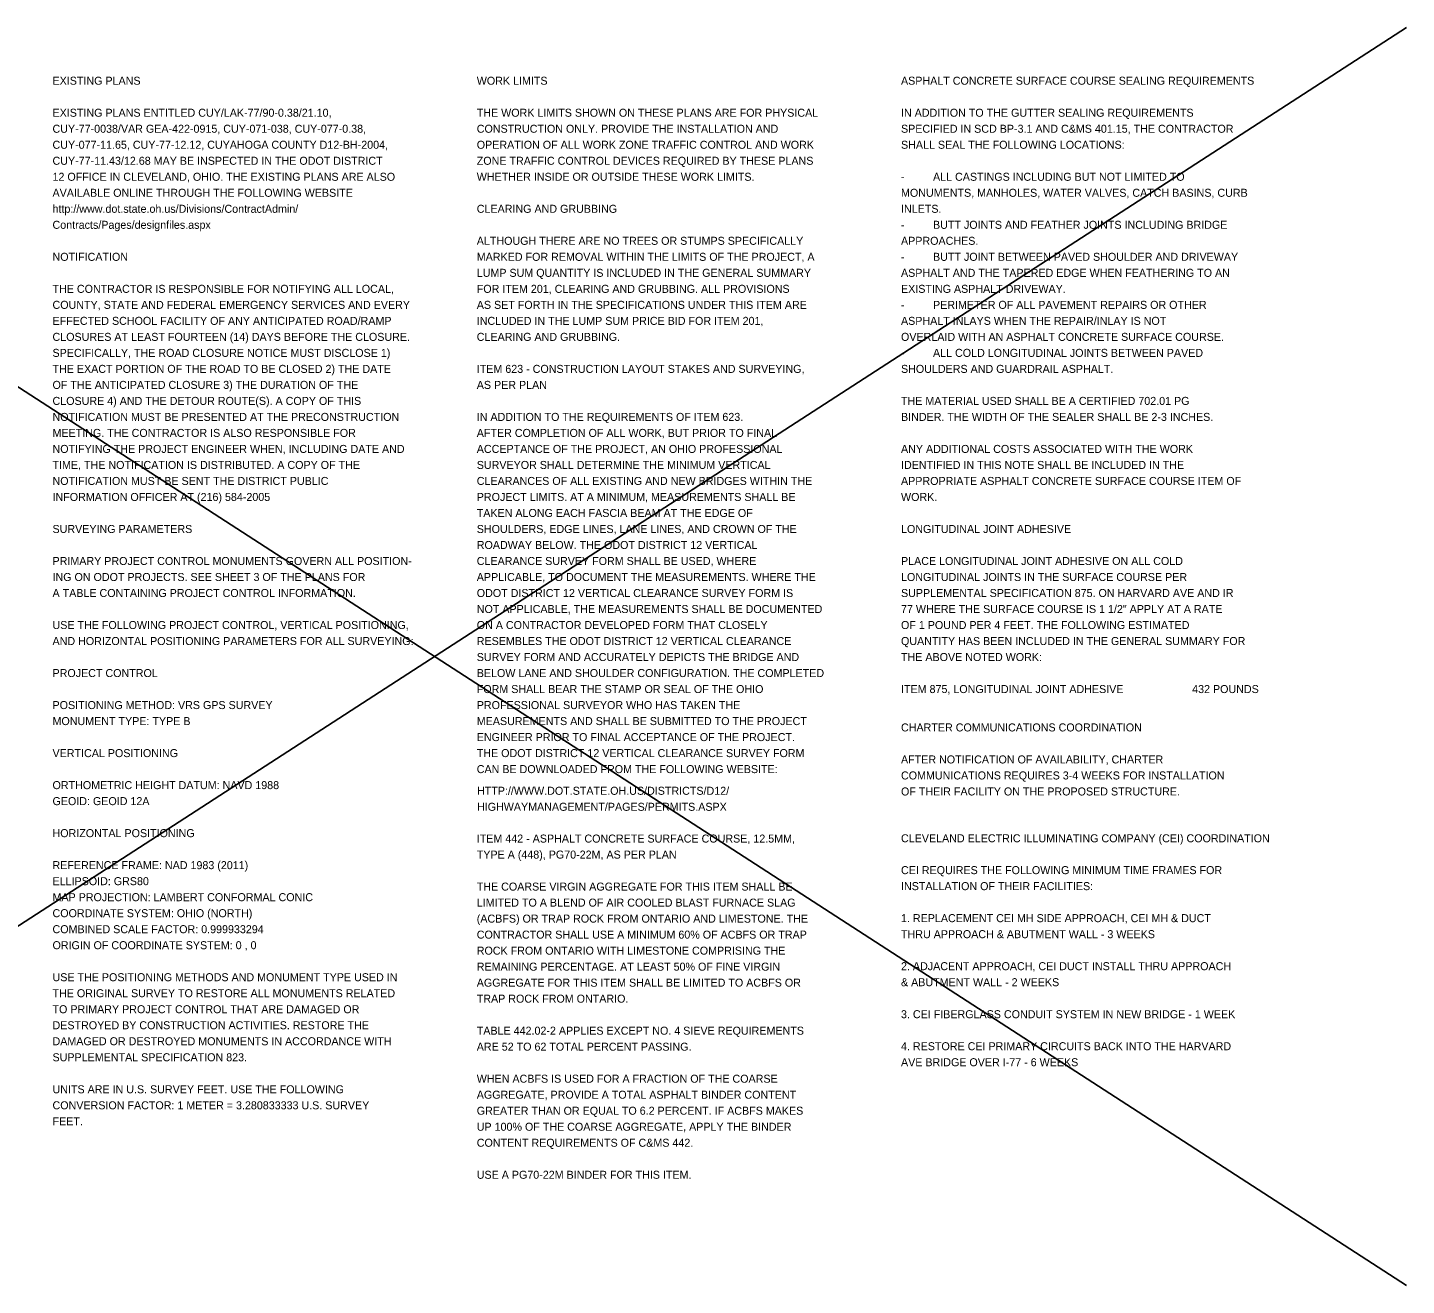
# Model space of a CAD drawing. Extents: x -9 to 100, y -25 to 48.
# Drawn here: x 10.02 to 34.14, y 25.8 to 47.8 of the extents above; entities that cross this region are included whole.
import ezdxf

# ---------------------------------------------------------------- set-up
doc = ezdxf.new("R2010")
doc.units = 0
doc.layers.add('Default', color=7, linetype='Continuous')
doc.layers.add('SH_Text', color=7, linetype='Continuous')

msp = doc.modelspace()

# ---------------------------------------------------------------- linework, layer by layer
at = {"layer": 'Default'}
for p, q in [((0.139, 47.801), (34.139, 25.801)), ((0.139, 25.801), (34.139, 47.801))]:
    msp.add_line(p, q, dxfattribs=at)

# ---------------------------------------------------------------- texts
at = {"layer": 'SH_Text'}
for s, p in [('EXISTING PLANS', (10.459, 46.801)), ('WORK LIMITS', (17.879, 46.801)), ('ASPHALT CONCRETE SURFACE COURSE SEALING REQUIREMENTS', (25.299, 46.801)), ('EXISTING PLANS ENTITLED CUY/LAK-77/90-0.38/21.10, ', (10.459, 46.241)), ('THE WORK LIMITS SHOWN ON THESE PLANS ARE FOR PHYSICAL', (17.879, 46.241)), ('IN ADDITION TO THE GUTTER SEALING REQUIREMENTS ', (25.299, 46.241)), ('CUY-77-0038/VAR GEA-422-0915, CUY-071-038, CUY-077-0.38, ', (10.459, 45.961)), ('CONSTRUCTION ONLY. PROVIDE THE INSTALLATION AND', (17.879, 45.961)), ('SPECIFIED IN SCD BP-3.1 AND C&MS 401.15, THE CONTRACTOR ', (25.299, 45.961)), ('CUY-077-11.65, CUY-77-12.12, CUYAHOGA COUNTY D12-BH-2004, ', (10.459, 45.681)), ('OPERATION OF ALL WORK ZONE TRAFFIC CONTROL AND WORK', (17.879, 45.681)), ('SHALL SEAL THE FOLLOWING LOCATIONS:', (25.299, 45.681)), ('CUY-77-11.43/12.68 MAY BE INSPECTED IN THE ODOT DISTRICT ', (10.459, 45.401)), ('ZONE TRAFFIC CONTROL DEVICES REQUIRED BY THESE PLANS', (17.879, 45.401)), ('12 OFFICE IN CLEVELAND, OHIO. THE EXISTING PLANS ARE ALSO ', (10.459, 45.121)), ('WHETHER INSIDE OR OUTSIDE THESE WORK LIMITS.', (17.879, 45.121)), ('-', (25.299, 45.121)), ('ALL CASTINGS INCLUDING BUT NOT LIMITED TO  ', (25.859, 45.121)), ('AVAILABLE ONLINE THROUGH THE FOLLOWING WEBSITE', (10.459, 44.841)), ('MONUMENTS, MANHOLES, WATER VALVES, CATCH BASINS, CURB ', (25.299, 44.841)), ('http://www.dot.state.oh.us/Divisions/ContractAdmin/', (10.459, 44.561)), ('CLEARING AND GRUBBING', (17.879, 44.561)), ('INLETS. ', (25.299, 44.561)), ('Contracts/Pages/designfiles.aspx', (10.459, 44.281)), ('BUTT JOINTS AND FEATHER JOINTS INCLUDING BRIDGE ', (25.859, 44.281)), ('ALTHOUGH THERE ARE NO TREES OR STUMPS SPECIFICALLY', (17.879, 44.001)), ('APPROACHES. ', (25.299, 44.001)), ('-', (25.299, 44.281)), ('NOTIFICATION', (10.459, 43.721)), ('MARKED FOR REMOVAL WITHIN THE LIMITS OF THE PROJECT, A', (17.879, 43.721)), ('-', (25.299, 43.721)), ('BUTT JOINT BETWEEN PAVED SHOULDER AND DRIVEWAY ', (25.859, 43.721)), ('LUMP SUM QUANTITY IS INCLUDED IN THE GENERAL SUMMARY', (17.879, 43.441)), ('ASPHALT AND THE TAPERED EDGE WHEN FEATHERING TO AN ', (25.299, 43.441)), ('THE CONTRACTOR IS RESPONSIBLE FOR NOTIFYING ALL LOCAL, ', (10.459, 43.161)), ('FOR ITEM 201, CLEARING AND GRUBBING. ALL PROVISIONS', (17.879, 43.161)), ('EXISTING ASPHALT DRIVEWAY. ', (25.299, 43.161)), ('COUNTY, STATE AND FEDERAL EMERGENCY SERVICES AND EVERY ', (10.459, 42.881)), ('AS SET FORTH IN THE SPECIFICATIONS UNDER THIS ITEM ARE', (17.879, 42.881)), ('-', (25.299, 42.881)), ('PERIMETER OF ALL PAVEMENT REPAIRS OR OTHER ', (25.859, 42.881)), ('EFFECTED SCHOOL FACILITY OF ANY ANTICIPATED ROAD/RAMP ', (10.459, 42.601)), ('INCLUDED IN THE LUMP SUM PRICE BID FOR ITEM 201,', (17.879, 42.601)), ('ASPHALT INLAYS WHEN THE REPAIR/INLAY IS NOT ', (25.299, 42.601)), ('CLOSURES AT LEAST FOURTEEN (14) DAYS BEFORE THE CLOSURE. ', (10.459, 42.321)), ('CLEARING AND GRUBBING.', (17.879, 42.321)), ('OVERLAID WITH AN ASPHALT CONCRETE SURFACE COURSE. ', (25.299, 42.321)), ('SPECIFICALLY, THE ROAD CLOSURE NOTICE MUST DISCLOSE 1) ', (10.459, 42.041)), ('-', (25.299, 42.041)), ('ALL COLD LONGITUDINAL JOINTS BETWEEN PAVED ', (25.859, 42.041)), ('THE EXACT PORTION OF THE ROAD TO BE CLOSED 2) THE DATE ', (10.459, 41.761)), ('ITEM 623 - CONSTRUCTION LAYOUT STAKES AND SURVEYING, ', (17.879, 41.761)), ('SHOULDERS AND GUARDRAIL ASPHALT. ', (25.299, 41.761)), ('OF THE ANTICIPATED CLOSURE 3) THE DURATION OF THE ', (10.459, 41.481)), ('AS PER PLAN', (17.879, 41.481)), ('CLOSURE 4) AND THE DETOUR ROUTE(S). A COPY OF THIS ', (10.459, 41.201)), ('THE MATERIAL USED SHALL BE A CERTIFIED 702.01 PG ', (25.299, 41.201)), ('NOTIFICATION MUST BE PRESENTED AT THE PRECONSTRUCTION ', (10.459, 40.921)), ('IN ADDITION TO THE REQUIREMENTS OF ITEM 623.', (17.879, 40.921)), ('BINDER. THE WIDTH OF THE SEALER SHALL BE 2-3 INCHES. ', (25.299, 40.921)), ('MEETING. THE CONTRACTOR IS ALSO RESPONSIBLE FOR ', (10.459, 40.641)), ('AFTER COMPLETION OF ALL WORK, BUT PRIOR TO FINAL ', (17.879, 40.641)), ('NOTIFYING THE PROJECT ENGINEER WHEN, INCLUDING DATE AND ', (10.459, 40.361)), ('ACCEPTANCE OF THE PROJECT, AN OHIO PROFESSIONAL ', (17.879, 40.361)), ('ANY ADDITIONAL COSTS ASSOCIATED WITH THE WORK ', (25.299, 40.361)), ('TIME, THE NOTIFICATION IS DISTRIBUTED. A COPY OF THE ', (10.459, 40.081)), ('SURVEYOR SHALL DETERMINE THE MINIMUM VERTICAL ', (17.879, 40.081)), ('IDENTIFIED IN THIS NOTE SHALL BE INCLUDED IN THE ', (25.299, 40.081)), ('NOTIFICATION MUST BE SENT THE DISTRICT PUBLIC ', (10.459, 39.801)), ('CLEARANCES OF ALL EXISTING AND NEW BRIDGES WITHIN THE ', (17.879, 39.801)), ('APPROPRIATE ASPHALT CONCRETE SURFACE COURSE ITEM OF ', (25.299, 39.801)), ('INFORMATION OFFICER AT (216) 584-2005', (10.459, 39.521)), ('PROJECT LIMITS. AT A MINIMUM, MEASUREMENTS SHALL BE ', (17.879, 39.521)), ('WORK. ', (25.299, 39.521)), ('TAKEN ALONG EACH FASCIA BEAM AT THE EDGE OF ', (17.879, 39.241)), ('SURVEYING PARAMETERS', (10.459, 38.961)), ('SHOULDERS, EDGE LINES, LANE LINES, AND CROWN OF THE ', (17.879, 38.961)), ('LONGITUDINAL JOINT ADHESIVE', (25.299, 38.961)), ('ROADWAY BELOW. THE ODOT DISTRICT 12 VERTICAL ', (17.879, 38.681)), ('PRIMARY PROJECT CONTROL MONUMENTS GOVERN ALL POSITION-', (10.459, 38.401)), ('CLEARANCE SURVEY FORM SHALL BE USED, WHERE ', (17.879, 38.401)), ('PLACE LONGITUDINAL JOINT ADHESIVE ON ALL COLD ', (25.299, 38.401)), ('ING ON ODOT PROJECTS. SEE SHEET 3 OF THE PLANS FOR', (10.459, 38.121)), ('APPLICABLE, TO DOCUMENT THE MEASUREMENTS. WHERE THE ', (17.879, 38.121)), ('LONGITUDINAL JOINTS IN THE SURFACE COURSE PER ', (25.299, 38.121)), ('A TABLE CONTAINING PROJECT CONTROL INFORMATION.', (10.459, 37.841)), ('ODOT DISTRICT 12 VERTICAL CLEARANCE SURVEY FORM IS ', (17.879, 37.841)), ('SUPPLEMENTAL SPECIFICATION 875. ON HARVARD AVE AND IR ', (25.299, 37.841)), ('NOT APPLICABLE, THE MEASUREMENTS SHALL BE DOCUMENTED ', (17.879, 37.561)), ('77 WHERE THE SURFACE COURSE IS 1 1/2" APPLY AT A RATE ', (25.299, 37.561)), ('USE THE FOLLOWING PROJECT CONTROL, VERTICAL POSITIONING,', (10.459, 37.281)), ('ON A CONTRACTOR DEVELOPED FORM THAT CLOSELY ', (17.879, 37.281)), ('OF 1 POUND PER 4 FEET. THE FOLLOWING ESTIMATED ', (25.299, 37.281)), ('AND HORIZONTAL POSITIONING PARAMETERS FOR ALL SURVEYING:', (10.459, 37.001)), ('RESEMBLES THE ODOT DISTRICT 12 VERTICAL CLEARANCE ', (17.879, 37.001)), ('QUANTITY HAS BEEN INCLUDED IN THE GENERAL SUMMARY FOR ', (25.299, 37.001)), ('SURVEY FORM AND ACCURATELY DEPICTS THE BRIDGE AND ', (17.879, 36.721)), ('THE ABOVE NOTED WORK:', (25.299, 36.721)), ('PROJECT CONTROL', (10.459, 36.441)), ('BELOW LANE AND SHOULDER CONFIGURATION. THE COMPLETED ', (17.879, 36.441)), ('FORM SHALL BEAR THE STAMP OR SEAL OF THE OHIO ', (17.879, 36.161)), ('ITEM 875, LONGITUDINAL JOINT ADHESIVE', (25.299, 36.161)), (' 432 POUNDS  ', (30.339, 36.161)), ('POSITIONING METHOD: VRS GPS SURVEY', (10.459, 35.881)), ('PROFESSIONAL SURVEYOR WHO HAS TAKEN THE ', (17.879, 35.881)), ('MONUMENT TYPE: TYPE B', (10.459, 35.601)), ('MEASUREMENTS AND SHALL BE SUBMITTED TO THE PROJECT ', (17.879, 35.601)), ('ENGINEER PRIOR TO FINAL ACCEPTANCE OF THE PROJECT.', (17.879, 35.321)), ('CHARTER COMMUNICATIONS COORDINATION', (25.299, 35.49)), ('VERTICAL POSITIONING', (10.459, 35.041)), ('THE ODOT DISTRICT 12 VERTICAL CLEARANCE SURVEY FORM ', (17.879, 35.041)), ('AFTER NOTIFICATION OF AVAILABILITY, CHARTER ', (25.299, 34.93)), ('CAN BE DOWNLOADED FROM THE FOLLOWING WEBSITE:', (17.879, 34.761)), ('COMMUNICATIONS REQUIRES 3-4 WEEKS FOR INSTALLATION ', (25.299, 34.65)), ('ORTHOMETRIC HEIGHT DATUM: NAVD 1988', (10.459, 34.481)), ('HTTP://WWW.DOT.STATE.OH.US/DISTRICTS/D12/', (17.883, 34.382)), ('OF THEIR FACILITY ON THE PROPOSED STRUCTURE.', (25.299, 34.37)), ('GEOID: GEOID 12A', (10.459, 34.201)), ('HIGHWAYMANAGEMENT/PAGES/PERMITS.ASPX', (17.883, 34.102)), ('HORIZONTAL POSITIONING', (10.459, 33.641)), ('ITEM 442 - ASPHALT CONCRETE SURFACE COURSE, 12.5MM, ', (17.879, 33.546)), ('CLEVELAND ELECTRIC ILLUMINATING COMPANY (CEI) COORDINATION', (25.299, 33.551)), ('TYPE A (448), PG70-22M, AS PER PLAN', (17.879, 33.266)), ('REFERENCE FRAME: NAD 1983 (2011)', (10.459, 33.081)), ('CEI REQUIRES THE FOLLOWING MINIMUM TIME FRAMES FOR ', (25.299, 32.994)), ('ELLIPSOID: GRS80', (10.459, 32.801)), ('THE COARSE VIRGIN AGGREGATE FOR THIS ITEM SHALL BE ', (17.879, 32.706)), ('INSTALLATION OF THEIR FACILITIES:', (25.299, 32.714)), ('MAP PROJECTION: LAMBERT CONFORMAL CONIC', (10.459, 32.521)), ('LIMITED TO A BLEND OF AIR COOLED BLAST FURNACE SLAG ', (17.879, 32.426)), ('COORDINATE SYSTEM: OHIO (NORTH)', (10.459, 32.241)), ('COMBINED SCALE FACTOR: 0.999933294', (10.459, 31.961)), ('(ACBFS) OR TRAP ROCK FROM ONTARIO AND LIMESTONE. THE ', (17.879, 32.146)), ('1. REPLACEMENT CEI MH SIDE APPROACH, CEI MH & DUCT ', (25.299, 32.154)), ('CONTRACTOR SHALL USE A MINIMUM 60% OF ACBFS OR TRAP ', (17.879, 31.866)), ('THRU APPROACH & ABUTMENT WALL - 3 WEEKS', (25.299, 31.874)), ('ORIGIN OF COORDINATE SYSTEM: 0 , 0', (10.459, 31.681)), ('ROCK FROM ONTARIO WITH LIMESTONE COMPRISING THE ', (17.879, 31.586)), ('REMAINING PERCENTAGE. AT LEAST 50% OF FINE VIRGIN ', (17.879, 31.306)), ('2. ADJACENT APPROACH, CEI DUCT INSTALL THRU APPROACH ', (25.299, 31.314)), ('USE THE POSITIONING METHODS AND MONUMENT TYPE USED IN', (10.459, 31.121)), ('AGGREGATE FOR THIS ITEM SHALL BE LIMITED TO ACBFS OR ', (17.879, 31.026)), ('& ABUTMENT WALL - 2 WEEKS', (25.299, 31.034)), ('THE ORIGINAL SURVEY TO RESTORE ALL MONUMENTS RELATED', (10.459, 30.841)), ('TRAP ROCK FROM ONTARIO.', (17.879, 30.746)), ('TO PRIMARY PROJECT CONTROL THAT ARE DAMAGED OR', (10.459, 30.561)), ('DESTROYED BY CONSTRUCTION ACTIVITIES. RESTORE THE', (10.459, 30.281)), ('3. CEI FIBERGLASS CONDUIT SYSTEM IN NEW BRIDGE - 1 WEEK', (25.299, 30.474)), ('TABLE 442.02-2 APPLIES EXCEPT NO. 4 SIEVE REQUIREMENTS ', (17.879, 30.186)), ('DAMAGED OR DESTROYED MONUMENTS IN ACCORDANCE WITH', (10.459, 30.001)), ('ARE 52 TO 62 TOTAL PERCENT PASSING.', (17.879, 29.906)), ('4. RESTORE CEI PRIMARY CIRCUITS BACK INTO THE HARVARD ', (25.299, 29.914)), ('SUPPLEMENTAL SPECIFICATION 823.', (10.459, 29.721)), ('AVE BRIDGE OVER I-77 - 6 WEEKS', (25.299, 29.634)), ('WHEN ACBFS IS USED FOR A FRACTION OF THE COARSE ', (17.879, 29.346)), ('UNITS ARE IN U.S. SURVEY FEET. USE THE FOLLOWING', (10.459, 29.161)), ('AGGREGATE, PROVIDE A TOTAL ASPHALT BINDER CONTENT ', (17.879, 29.066)), ('CONVERSION FACTOR: 1 METER = 3.280833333 U.S. SURVEY', (10.459, 28.881)), ('FEET.', (10.459, 28.601)), ('GREATER THAN OR EQUAL TO 6.2 PERCENT. IF ACBFS MAKES ', (17.879, 28.786)), ('UP 100% OF THE COARSE AGGREGATE, APPLY THE BINDER ', (17.879, 28.506)), ('CONTENT REQUIREMENTS OF C&MS 442.', (17.879, 28.226)), ('USE A PG70-22M BINDER FOR THIS ITEM.', (17.879, 27.666))]:
    msp.add_text(s, height=0.14, dxfattribs=at).set_placement(p)

doc.saveas('drawing.dxf')
